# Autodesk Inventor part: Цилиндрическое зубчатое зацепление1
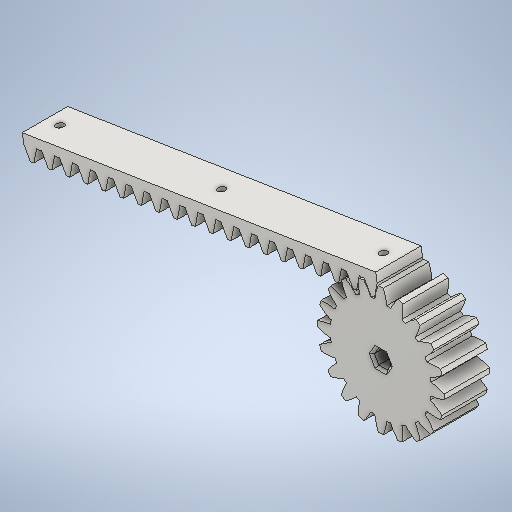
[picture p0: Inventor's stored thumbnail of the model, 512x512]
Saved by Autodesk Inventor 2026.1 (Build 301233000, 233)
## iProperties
CustomPartVersion: 1
Created: 2026-01
Part Number: Цилиндрическое зубчатое зацепление1
Material: Steel
Document SubType Name: Modeling
Designer: Yury Melnikov
Categories: <?xml version="1.0" encoding="UTF-16"?> <MemberInstance><Categories><FamilyTemplate><FamilyTemplateParameter ValueType="xs:double" Id="1" ObjectReferenceKey="da
Density: 1 g/cm^3
Appearance: Steel
Author: Yury Melnikov
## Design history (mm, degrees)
sketch "Sketch1"
  geometry: C1 r 21.01 at (0, 0)
  constraints: 1 centre point
  dimensions: "d0" = 42.02 diameter of C1 (= da_da)
extrude "Extrusion1" new body sketch "Sketch1" distance "d1" = 15 (= da_b); taper "d2" = 0 deg
workplane "Work Plane2"
feature "Средний диаметр" dims "d4" = 10, "d5" = 0
workplane "Work Plane8"
workplane "Work Plane9"
feature "Цилиндрическое зубчатое зацепление" dims "da_b" = 15, "da_d" = 38.2, "da_aw" = 73.535, "da_da" = 42.02, "da_df" = 33.425, "da_dw" = 38.2, angle "da_beta" = 0 deg, "da_lefttooth" = 0, "da_righttooth" = 0
sketch "Эскиз3"
  geometry: L1 (-5.461, 20.743)-(-3.244, 16.743); L2 (-3.244, 16.743)-(-2.089, 16.926); L3 (-2.089, 16.926)-(-1.216, 21.415); L4 (-1.216, 21.415)-(-5.461, 20.743); L5 (-5.703, 20.221)-(-0.825, 20.994); L6 (-3.339, 21.079)-(-3.264, 20.607); L7 (-118.08, 2.906)-(-1.216, 21.415); L8 (-1.216, 21.415)-(-1.686, 24.378); L9 (-1.686, 24.378)-(-118.55, 5.869); L10 (-118.55, 5.869)-(-118.08, 2.906); L11 (-11.388, 19.804)-(-9.171, 15.804); L12 (-9.171, 15.804)-(-8.016, 15.987); L13 (-11.63, 19.282)-(-6.752, 20.055); L14 (-8.016, 15.987)-(-7.144, 20.476); L15 (-17.316, 18.865)-(-15.098, 14.865); L16 (-15.098, 14.865)-(-13.944, 15.048); L17 (-17.558, 18.344)-(-12.68, 19.116); L18 (-13.944, 15.048)-(-13.071, 19.538); L19 (-23.243, 17.927)-(-21.026, 13.927); L20 (-21.026, 13.927)-(-19.871, 14.11); L21 (-23.485, 17.405)-(-18.607, 18.177); L22 (-19.871, 14.11)-(-18.998, 18.599); L23 (-29.17, 16.988)-(-26.953, 12.988); L24 (-26.953, 12.988)-(-25.798, 13.171); L25 (-29.412, 16.466)-(-24.534, 17.239); L26 (-25.798, 13.171)-(-24.926, 17.66); L27 (-35.098, 16.049)-(-32.88, 12.049); L28 (-32.88, 12.049)-(-31.726, 12.232); L29 (-35.34, 15.527)-(-30.462, 16.3); L30 (-31.726, 12.232)-(-30.853, 16.721); L31 (-41.025, 15.11)-(-38.808, 11.11); L32 (-38.808, 11.11)-(-37.653, 11.293); L33 (-41.267, 14.588)-(-36.389, 15.361); L34 (-37.653, 11.293)-(-36.78, 15.782); L35 (-46.952, 14.171)-(-44.735, 10.171); L36 (-44.735, 10.171)-(-43.58, 10.354); L37 (-47.194, 13.65)-(-42.316, 14.422); L38 (-43.58, 10.354)-(-42.708, 14.844); L39 (-52.88, 13.233)-(-50.662, 9.233); L40 (-50.662, 9.233)-(-49.508, 9.416); L41 (-53.122, 12.711)-(-48.244, 13.483); L42 (-49.508, 9.416)-(-48.635, 13.905); L43 (-58.807, 12.294)-(-56.59, 8.294); L44 (-56.59, 8.294)-(-55.435, 8.477); L45 (-59.049, 11.772)-(-54.171, 12.545); L46 (-55.435, 8.477)-(-54.562, 12.966); L47 (-64.734, 11.355)-(-62.517, 7.355); L48 (-62.517, 7.355)-(-61.362, 7.538); L49 (-64.976, 10.833)-(-60.098, 11.606); L50 (-61.362, 7.538)-(-60.49, 12.027); L51 (-70.662, 10.416)-(-68.444, 6.416); L52 (-68.444, 6.416)-(-67.29, 6.599); L53 (-70.904, 9.894)-(-66.026, 10.667); L54 (-67.29, 6.599)-(-66.417, 11.088); L55 (-76.589, 9.477)-(-74.372, 5.478); L56 (-74.372, 5.478)-(-73.217, 5.66); L57 (-76.831, 8.956)-(-71.953, 9.728); L58 (-73.217, 5.66)-(-72.344, 10.15); L59 (-82.516, 8.539)-(-80.299, 4.539); L60 (-80.299, 4.539)-(-79.144, 4.722); L61 (-82.758, 8.017)-(-77.88, 8.789); L62 (-79.144, 4.722)-(-78.272, 9.211); L63 (-88.444, 7.6)-(-86.226, 3.6); L64 (-86.226, 3.6)-(-85.072, 3.783)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; C1 r 19.1 at (0, 0); A1 r 21.01 centre (0, 0) between (-5.703, 20.221) and (-7.272, 19.711) reference; A2 r 15.832 centre (13.773, 14.865) between (-0.825, 20.994) and (-1.964, 16.597) reference; 58 further points
  constraints: 210 end point, 4 parallel, 3 coincident, 2 midpoint, 2 perpendicular, 1 centre point, 1 collinear, 1 equal length, 265 other
  dimensions: "d49" = 38.2 diameter of C1; "d50" = 70 deg angle of L3 L4; "d51" = 4.2975 distance between parallel lines of L2 L4; "d52" = 0.4775 distance between parallel lines of L5 L4; "d55" = 4.2975 distance of L3.end L1.start; "d56" = 3 distance of L3.end L8.end; "d59" = 6.00122 distance of L1.start L11.start; "d76" = 6.00122 distance of L1.start L88.start (derived)
extrude "Выдавливание2" new body sketch "Эскиз3" distance "d71" = 15; taper "d72" = 0 deg
sketch "Эскиз4"
  geometry: L1 (-2.565, 7.5)-(51.595, 7.5); L2 (51.595, 7.5)-(105.755, 7.5); L3 (-7.565, 15)-(-7.565, 0) reference; L4 (110.755, 15)-(110.755, 0) reference; C1 r 1.25 at (-2.565, 7.5); C2 r 1.25 at (51.595, 7.5); C3 r 1.25 at (105.755, 7.5); 3 further points
  constraints: 4 end point, 3 centre point, 2 collinear, 2 equal radius, 2 midpoint, 1 horizontal, 1 horizontal alignment
  dimensions: "d81" = 5 distance from line of L2.end L4; "d82" = 5 distance of L1.start point (-7.565, 7.5); "d83" = 2.5 diameter of C3
extrude "Выдавливание3" cut sketch "Эскиз4" distance "d84" = 10; taper "d85" = 0 deg
node "РабПлоскость11"
sketch "Эскиз5"
  geometry: L1 (-26.738, 0)-(-26.738, 15) reference; C1 r 1.25 at (-5, 7.5) reference; C2 r 1.25 at (-59.16, 7.5) reference; C3 r 1.25 at (-113.321, 7.5) reference; C4 r 2.6 at (-113.321, 7.5); C5 r 2.6 at (-59.16, 7.5); C6 r 2.6 at (-5, 7.5); 1 further point
  constraints: 3 centre point, 2 equal radius
  dimensions: "d87" = 5.2 diameter of C6
extrude "Выдавливание4" cut sketch "Эскиз5" distance "d88" = 35.95; taper "d89" = 0 deg
chamfer "Фаска1" distance "d90" = 1; stored, may be unused: second distance "d91" = 2, angle "d92" = 45 deg
sketch "Эскиз6"
  geometry: L1 (-1.443, 2.5)-(1.443, 2.5); L2 (1.443, 2.5)-(2.887, 0); L3 (2.887, 0)-(1.443, -2.5); L4 (1.443, -2.5)-(-1.443, -2.5); L5 (-1.443, -2.5)-(-2.887, 0); L6 (-2.887, 0)-(-1.443, 2.5); 2 further points
  constraints: 12 end point, 1 coincident, 1 horizontal, 13 other
  dimensions: "d93" = 5 distance between parallel lines of L4 L1
extrude "Выдавливание5" cut sketch "Эскиз6" distance "d94" = 35.95; taper "d95" = 0 deg
chamfer "Фаска2" distance "d96" = 0.8; stored, may be unused: second distance "d97" = 2, angle "d98" = 45 deg
body "Solid1"
sketch "Sketch2"
  geometry: C1 r 21.01 at (0, 0) reference; C2 r 19.1 at (0, 0)
  constraints: 1 centre point, 1 coincident
  dimensions: "d3" = 38.2 diameter of C2 (= da_d)
body "Srf1"
node "Эскиз — прямоугольный массив1" dims "d59" = 6.00122, "d62" = 10
node "Эскиз — прямоугольный массив3" dims "d76" = 6.00122 (derived), "d79" = 10
node "Твердое тело2"
other parameters: "d16" = 73.535 (= da_aw), "d17" = 0, "d34" = 9 deg (computed from da_z), "d39" = 0, "d41" = 0, "d43" = 73.535 (= da_aw), "d46" = 73.535 (= da_aw), "d47" = 0, "d48" = 0, "d86" = -38.25
